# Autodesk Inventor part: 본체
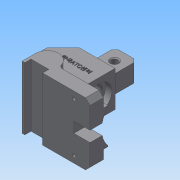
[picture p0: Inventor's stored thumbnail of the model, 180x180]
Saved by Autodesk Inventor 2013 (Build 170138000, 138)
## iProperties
Created: 2016-11
Part Number: 본체
Material: 일반
Document SubType Name: Modeling
Designer: Administrator
Density: 1 g/cm^3
Author: Administrator
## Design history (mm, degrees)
sketch "스케치1"
  geometry: L1 (0, 0)-(63, 0); L2 (63, 0)-(63, 20); L3 (63, 20)-(0, 20); L4 (0, 20)-(0, 0)
  constraints: 8 end point, 2 perpendicular, 1 horizontal, 1 parallel
  dimensions: "d0" = 63 distance of L1.start L1.end; "d1" = 20 distance of L1.end L2.end
extrude "돌출1" new body sketch "스케치1" distance "d2" = 70; taper "d3" = 0 deg
sketch "스케치2"
  geometry: L1 (0, 0)-(63, 0) reference; L2 (0, 20)-(0, 0) reference; L3 (0, 0)-(0, 15); L4 (-13, 15)-(-13, 0); L5 (-13, 0)-(-10, 0); L6 (-10, 0)-(-10, 7); L7 (-10, 7)-(10, 7); L8 (10, 7)-(10, 0); A1 r 13 centre (0, 15) between (10, 6.693) and (-13, 15)
  constraints: 12 end point, 4 perpendicular, 3 point on line, 2 point on circle, 1 centre point, 1 coincident, 1 parallel, 1 tangent
extrude "돌출2" join sketch "스케치2" distance "d9" = 70; taper "d10" = 0 deg
sketch "스케치3"
  geometry: L1 (0, 7)-(0, 0) reference; L2 (0, 0)-(63, 0) reference; L3 (-10, 0)-(10, 0); L4 (10, 0)-(10, 7); L5 (10, 7)-(0, 7); L6 (0, 7)-(0, 0)
  constraints: 8 end point, 1 collinear, 1 perpendicular, 1 point on line
  dimensions: "d11" = 20 distance of L3.start L3.end; "d12" = 7 distance of L3.end L4.end
extrude "돌출3" cut sketch "스케치3" distance "d13" = 70; taper "d14" = 0 deg
node "작업 평면1"
sketch "스케치4"
  geometry: L1 (10, 7)-(-10, 7) reference; L2 (-10, 7)-(-10, 0) reference; L3 (-10, 0)-(-13, 0) reference; L4 (-13, 0)-(-13, 15) reference; L5 (12, 20)-(63, 20) reference; L6 (63, 20)-(63, 0) reference; L7 (63, 0)-(10, 0) reference; L8 (10, 0)-(10, 7) reference; L9 (31, 60)-(31, 20); L10 (-9, 60)-(-27, 42); L11 (-27, 42)-(-27, 12); L12 (-27, 12)-(-13, 12); L13 (-9, 60)-(31, 60); A1 r 13 centre (0, 15) between (12, 20) and (-13, 15) reference; 1 further point
  constraints: 10 end point, 2 perpendicular, 2 point on line, 1 parallel
extrude "돌출4" join sketch "스케치4" stored distance "d23" = 40; taper "d24" = 0 deg
sketch "스케치5"
  geometry: L1 (63, 0)-(63, 20) reference; L2 (63, 20)-(12, 20) reference; L3 (-13, 15)-(-13, 0) reference; L4 (63, 15)-(13, 15); L5 (12, 20)-(63, 20); L6 (63, 20)-(63, 15); L7 (13, 15)-(63, 15); A1 r 13 centre (0, 15) between (12, 20) and (-13, 15) reference; A2 r 13 centre (0, 15) between (13, 15) and (12, 20); 1 further point
  constraints: 10 end point, 3 collinear, 2 point on circle, 1 centre point, 1 coincident, 1 point on line
extrude "돌출5" cut sketch "스케치5" distance "d26" = 15; taper "d27" = 0 deg
sketch "스케치6"
  geometry: L1 (-10, 7)-(10, 7) reference; L2 (13, 0)-(13, 15) reference; L3 (-12, 20)-(-63, 20) reference; L4 (-63, 20)-(-63, 0) reference; L5 (-10, 0)-(-10, 7) reference; L6 (-63, 0)-(-63, 7); L7 (-63, 15)-(-13, 15); A1 r 13 centre (0, 15) between (13, 15) and (-12, 20) reference; A2 r 13 centre (0, 15) between (-10, 6.693) and (13, 15); A3 r 13 centre (0, 15) between (-12, 20) and (-13, 15); 1 further point
  constraints: 6 end point, 4 point on circle, 3 point on line, 2 centre point, 1 coincident, 1 perpendicular
  dimensions: "d28" = 15 distance of L4.end L7.start
extrude "돌출6" cut sketch "스케치6" distance "d29" = 15; taper "d30" = 0 deg
sketch "스케치7"
  geometry: L1 (0, -5)-(0, -8) reference; L2 (0, -8)-(40, -8) reference; L3 (40, -8)-(40, -5) reference; L4 (40, -5)-(55, -5) reference; L5 (55, -20)-(55, -5) reference; L6 (-15, -20)-(55, -20) reference; L7 (-15, -5)-(-15, -20) reference; L8 (-15, -5)-(0, -5) reference; L9 (20, -20)-(20, 22); C1 r 14.5 at (20, 22); 1 further point
  constraints: 2 end point, 1 centre point, 1 coincident, 1 midpoint, 1 perpendicular
  dimensions: "d31" = 42 distance of L9.start L9.end; "d32" = 29 diameter of C1
extrude "돌출7" cut sketch "스케치7" distance "d33" = 7; taper "d34" = 0 deg
sketch "스케치8"
  geometry: C1 r 14.5 at (0, 0) reference; C2 r 10 at (0, 0); 1 further point
  constraints: 1 centre point, 1 coincident
  dimensions: "d35" = 20 diameter of C2
extrude "돌출8" cut sketch "스케치8" stored distance "d36" = 7; taper "d37" = 0 deg
sketch "스케치9"
  geometry: L1 (55, 60)-(15, 60) reference; L2 (15, 20)-(15, 60) reference; L3 (55, 20)-(15, 20) reference; L4 (55, 60)-(55, 20) reference; C1 r 14.5 at (35, 42) reference; C2 r 29 at (35, 42)
  constraints: 1 centre point, 1 coincident
  dimensions: "d38" = 58 diameter of C2
extrude "돌출9" cut sketch "스케치9" distance "d39" = 18; taper "d40" = 0 deg
sketch "스케치10"
  geometry: L1 (0, 0)-(70, 0) reference; L2 (35, 0)-(41, 0); L3 (41, 0)-(41, 13.627); L4 (35, 0)-(29, 0); L5 (29, 0)-(29, 13.627); A1 r 29 centre (35, 42) between (16.106, 20) and (53.894, 20) reference
  constraints: 8 end point, 2 perpendicular, 2 point on circle, 2 point on line, 1 midpoint
extrude "돌출10" cut sketch "스케치10" distance "d43" = 18; taper "d44" = 0 deg
sketch "스케치11"
  geometry: L1 (-22, 55)-(-22, 15) reference; L2 (18, 15)-(-22, 15) reference; L3 (18, 55)-(18, 15) reference; L4 (-22, 55)-(18, 55) reference; 2 further points
hole "구멍1" sketch "스케치11" at (32, 7.5) diameter "d47" = 3.459; stored, may be unused: countersink angle "d51" = 90 deg, drill point angle "d53" = 118 deg; dims "d48" = 6, "d49" = 4, "d50" = 2, "d52" = 8
sketch "스케치12"
  geometry: L1 (-13, 12)-(-13, 15) reference; L2 (-13, 12)-(-27, 12) reference; L3 (-27, 12)-(-27, 42) reference; L4 (-27, 42)-(-9, 60) reference; L5 (-9, 60)-(31, 60) reference; L6 (31, 60)-(31, 20) reference; L7 (63, 20)-(31, 20) reference; L8 (63, 15)-(63, 20) reference; L9 (13, 15)-(63, 15) reference; L10 (31, 60)-(26, 60); L11 (13, 15)-(63, 15) reference; L12 (63, 15)-(63, 0) reference; L13 (63, 0)-(10, 0) reference; L14 (10, 0)-(10, 7) reference; L15 (10, 7)-(-10, 7) reference; L16 (-10, 7)-(-10, 0) reference; L17 (-10, 0)-(-13, 0) reference; L18 (-13, 0)-(-13, 15) reference; L19 (26, 90)-(26, 60); L20 (26, 90)-(1, 90); L21 (1, 90)-(1, 60); A1 r 13 centre (0, 15) between (13, 15) and (-13, 15) reference; A2 r 13 centre (0, 15) between (13, 15) and (-13, 15) reference; 1 further point
  constraints: 8 end point, 2 perpendicular, 2 point on line
  dimensions: "d56" = 25 distance of L19.start L20.end
extrude "돌출11" join sketch "스케치12" stored distance "d57" = 20; taper "d58" = 0 deg
sketch "스케치13"
  geometry: L1 (26, 60)-(26, 90) reference; L2 (1, 90)-(1, 60) reference; L3 (26, 77)-(1, 77); C1 r 4 at (13.5, 77); 1 further point
  constraints: 2 end point, 2 point on line, 1 centre point, 1 midpoint
  dimensions: "d61" = 8 diameter of C1
extrude "돌출12" cut sketch "스케치13" distance "d62" = 20; taper "d63" = 0 deg
chamfer "모따기1" distance "d64" = 4; stored, may be unused: second distance "d65" = 2, angle "d66" = 45 deg
chamfer "모따기2" distance "d67" = 5; stored, may be unused: second distance "d68" = 2, angle "d69" = 45 deg
fillet "모깎기1" dims "d70" = 5, "d71" = 3
chamfer "모따기3" distance "d72" = 1; stored, may be unused: second distance "d73" = 2, angle "d74" = 45 deg
sketch "스케치14"
  geometry: L1 (-12.291, 46.916)-(24.291, 46.916); L2 (24.291, 46.916)-(24.291, 37.084); L3 (24.291, 37.084)-(-12.291, 37.084); L4 (-12.291, 37.084)-(-12.291, 46.916); 1 further point
  constraints: 2 other
feature "엠보싱1" sketch "스케치14" dims "d0" = 63, "d1" = 20, "d77" = 0.5, "d78" = 0
node "솔리드1"
mirror "대칭1"
node "투영된 루프1"
node "투영된 루프2"
node "투영된 루프3"
node "투영된 루프4"
node "투영된 루프5"
node "투영된 루프6"
other parameters: "d15" = -35
